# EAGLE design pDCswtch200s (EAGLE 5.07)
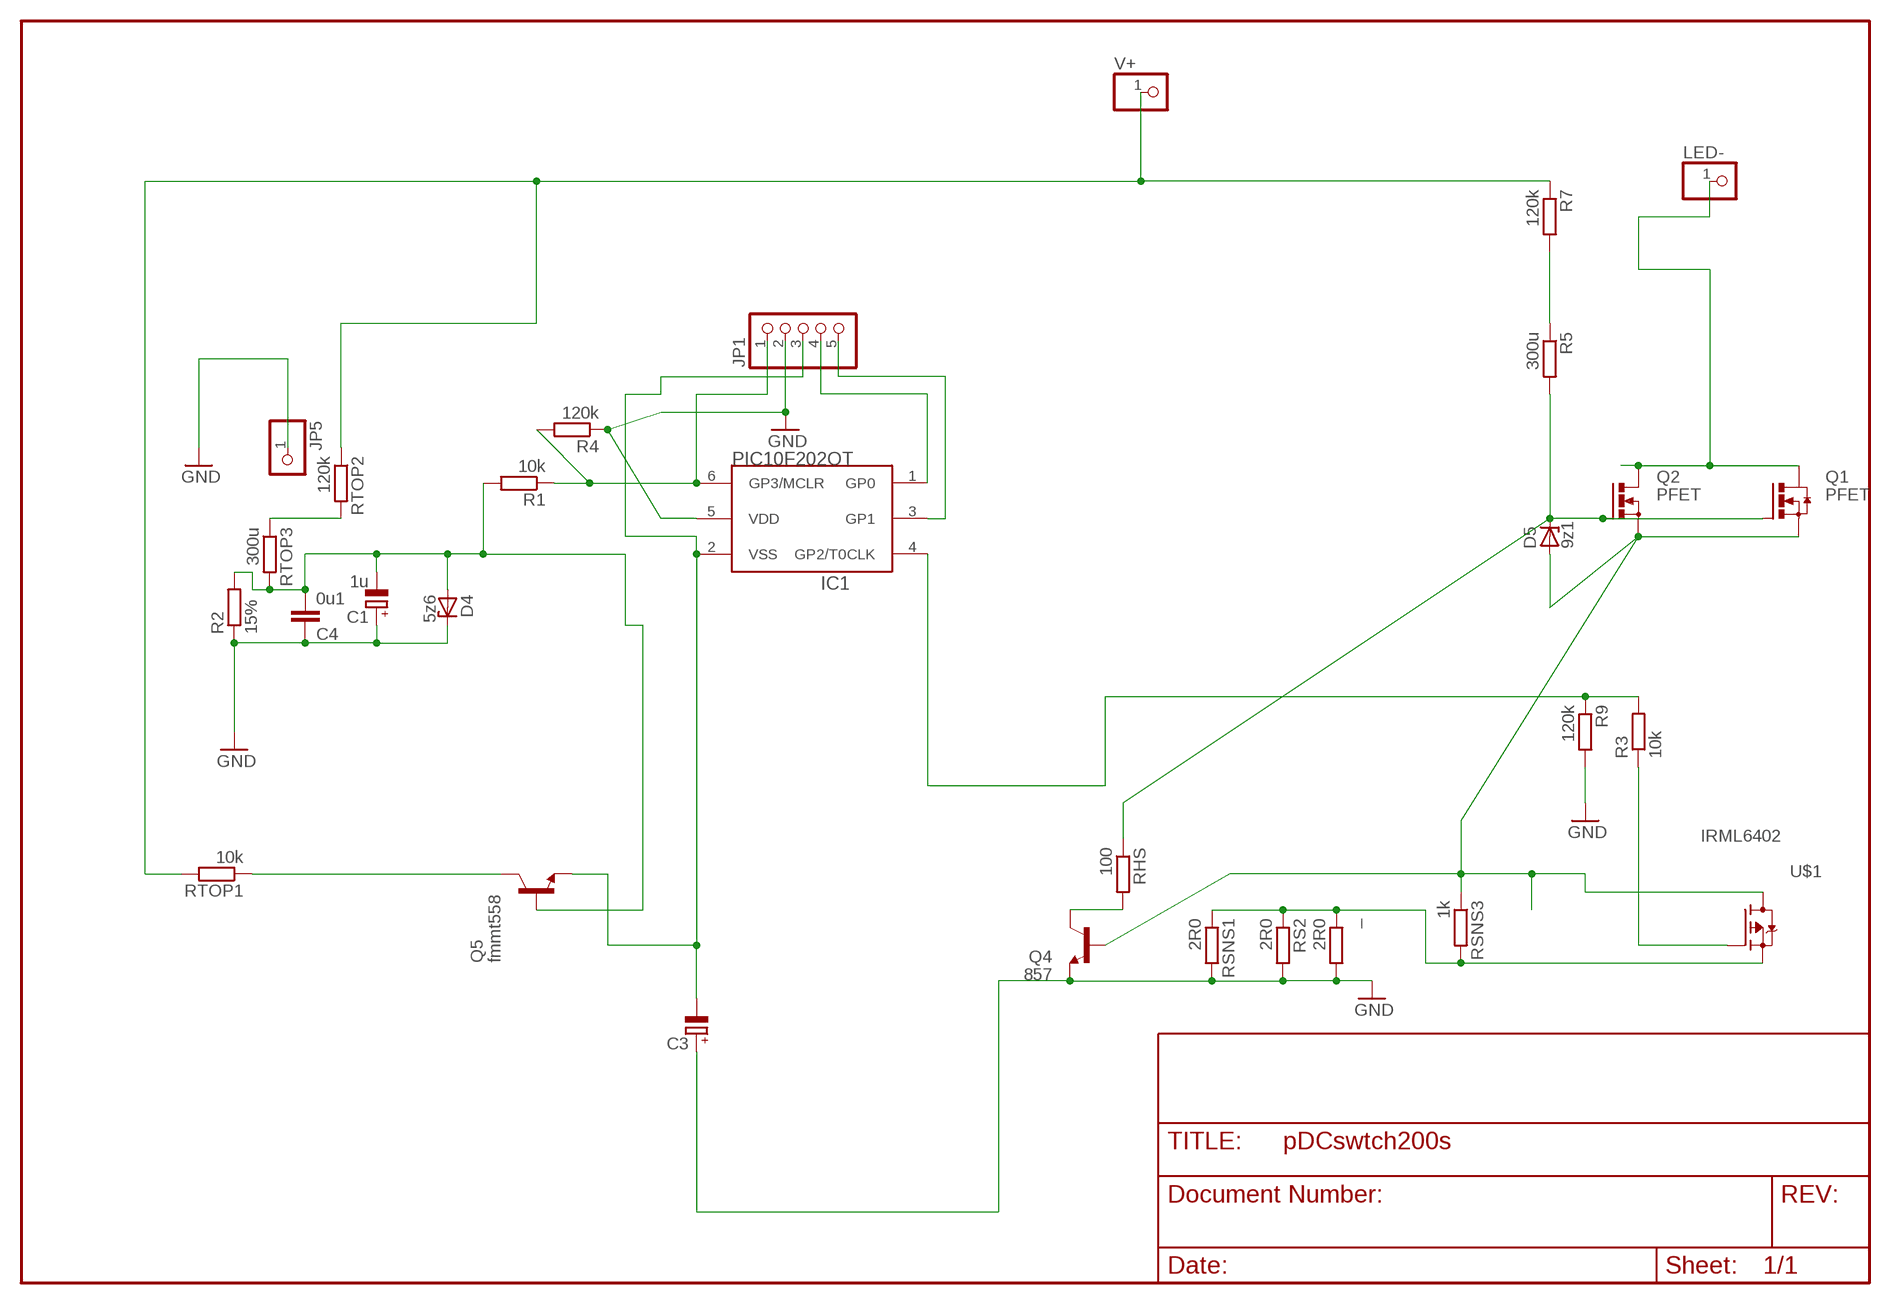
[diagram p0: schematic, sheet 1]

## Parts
_  2R0  R-EU_R1210  [R1210]
C1  1u  CPOL-EUSMCA  [SMC_A]
C3  CPOL-EUE2,5-6E  [E2,5-6E]
C4  0u1  C-EUC0805  [C0805]
D4  5z6  ZENER-DIODESOD80C  [SOD80C]
D5  9z1  ZENER-DIODESOD80C  [SOD80C]
IC1  PIC10F202OT  [SOT23-6]
JP1  PINHD-1X5/90  [1X05/90]
JP5  PINHD-1X11MM6  [1X1MM8]
LED-  PINHD-1X11MM6  [1X1MM8]
Q1  PFET  N-HEXFET_DPAK-  [TO252]
Q2  PFET  BUZ11BV  [TO220BV]
Q4  857  BC847ASMD  [SOT23]
Q5  fmmt558  BC847ALT1SMD  [SOT23]
R1  10k  R-EU_R0805  [R0805]
R2  15%  R-EU_R0805  [R0805]
R3  10k  R-EU_R0805  [R0805]
R4  120k  R-EU_R0805  [R0805]
R5  300u  R-EU_R1206  [R1206]
R7  120k  R-EU_R1206  [R1206]
R9  120k  R-EU_R0805  [R0805]
RHS  100  R-EU_0204/3  [0204/3]
RS2  2R0  R-EU_R1206  [R1206]
RSNS1  2R0  R-EU_R2512  [R2512]
RSNS3  1k  R-EU_R1206  [R1206]
RTOP1  10k  R-EU_R1206  [R1206]
RTOP2  120k  R-EU_R1206  [R1206]
RTOP3  300u  R-EU_R1206  [R1206]
U$1  IRML6402  IRML6402SOT23  [SOT23]
V+  PINHD-1X11MM6  [1X1MM8]

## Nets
BSW1: _.1 RS2.1 RSNS1.1 RSNS3.2 U$1.2(S)
C: Q5.3(C) RTOP1.1
CB: C1.- C4.2 D4.A Q5.1(B) R1.2 R2.2 RTOP3.2
G: D5.C Q1.1(G) Q2.G R5.2 RHS.1
GND: _.2 C1.+ C3.+ C4.1 D4.C IC1.5(VDD) JP1.2 JP5.1 Q4.2(E) R2.1 R4.1 R9.2 RS2.2 RSNS1.2
GP2: IC1.4(GP2/T0CLK) R3.2 R9.1
LED+: LED-.1 Q1.3(D) Q2.D
N$3: IC1.6(GP3/MCLR) JP1.1 R1.1 R4.2
N$4: R5.1 R7.2
N$5: R3.1 U$1.1(G)
N$7: Q4.3(C) RHS.2
N$9: RTOP2.2 RTOP3.1
N$10: IC1.1(GP0) JP1.4
N$12: IC1.3(GP1) JP1.5
S: D5.A Q1.2(S) Q2.S Q4.1(B) RSNS3.1 U$1.3(D)
VPLUS: R7.1 RTOP1.2 RTOP2.1 V+.1
VSS-: C3.- IC1.2(VSS) JP1.3 Q5.2(E)

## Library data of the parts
_ R3 R5 R7 RHS RS2 RSNS1 RSNS3 RTOP1-RTOP3 = rcl:R-EU_: RESISTOR, European symbol
C1 C3 = rcl:CPOL-EU: POLARIZED CAPACITOR, European symbol
C4 = rcl:C-EU: CAPACITOR, European symbol
D4 D5 = diode:ZENER-DIODE: Z-Diode
IC1 = microchip-5:PIC10F20*: uPC nW 0,25/0,5k Program Flash memory
JP1 = pinhead:PINHD-1X5: PIN HEADER
JP5 LED- V+ = pinhead:PINHD-1X1: PIN HEADER
Q1 = transistor-power:N-HEXFET_?-*: HEXFET® Power MOSFET
Q2 = transistor-power:BUZ11: N-CHANNEL MOS FET
Q4 Q5 = transistor-npn:BC847*: NPN Transistor
R1 R2 R4 R9 = rcl-2:R-EU_: RESISTOR, European symbol
U$1 = transistor-fet:IRML6402

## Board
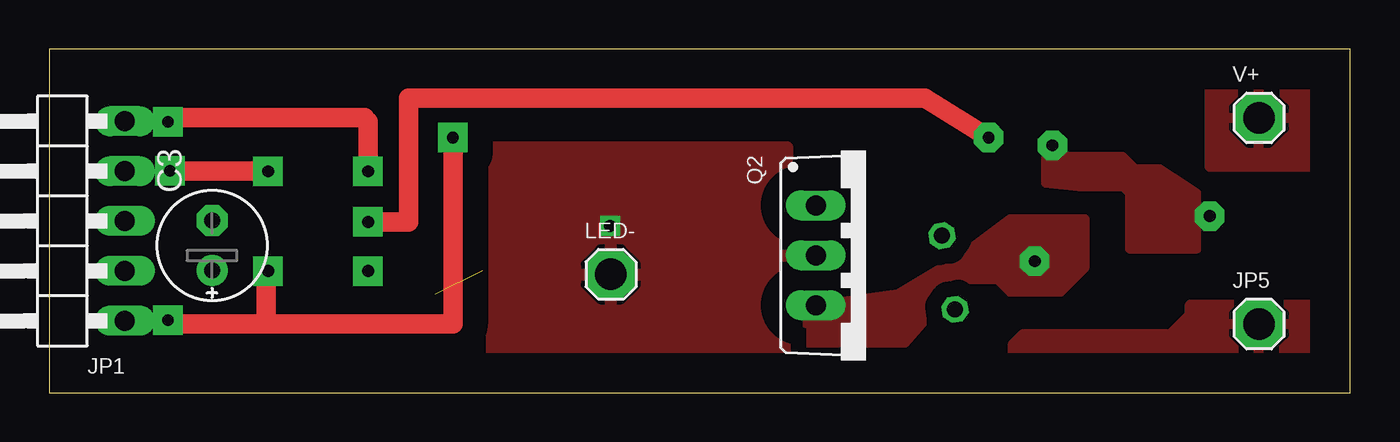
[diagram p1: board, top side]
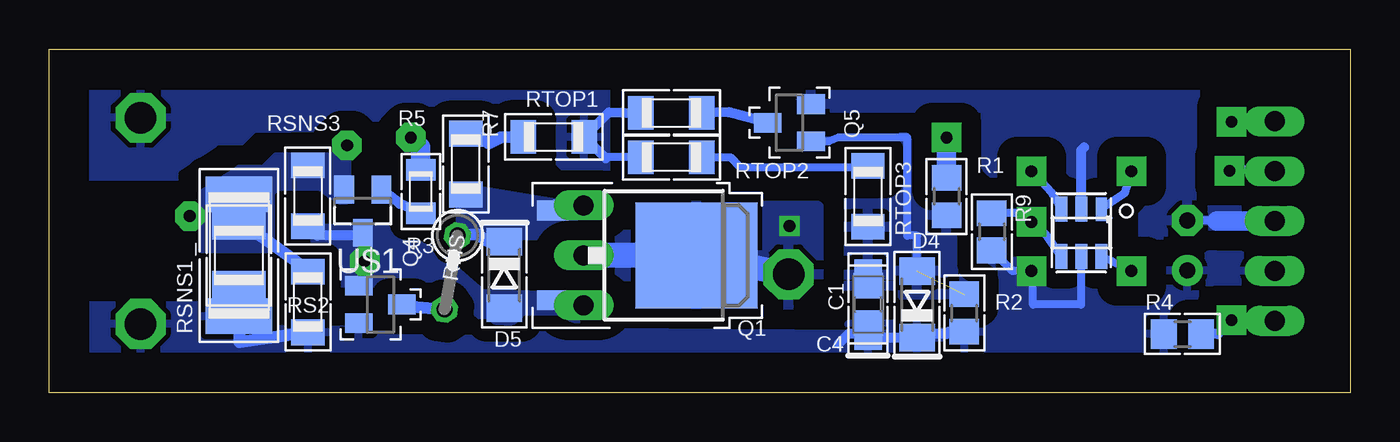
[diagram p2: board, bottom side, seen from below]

Size 66.2 x 17.5 mm. Coordinates in mm from the lower left corner, seen from the top.
Outline: 0,0 66.2,0 66.2,17.5 0,17.5 0,0
Copper layers (1*16): Top 0.035mm / dielectric 1.5mm / Bottom 0.035mm
Design rules "default *": minimum track width 10mil, minimum drill 24mil, track to track 8mil, track to pad 8mil, pad to pad 8mil, via to via 8mil, smd to smd 8mil, copper to edge 80mil, drill to drill 8mil, minimum pad ring 10mil, minimum via ring 8mil, stop-mask expansion 4mil, vias tented up to drill 0mil, thermal gap 10mil

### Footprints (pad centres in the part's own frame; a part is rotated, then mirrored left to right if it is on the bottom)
R1210 = smd 1.4 x 2.7: 1 -1.5,0; 2 1.5,0
SMC_A = smd 1.6 x 1.4: + -1.5,0; - 1.5,0
E2,5-6E = drill 0.813 pad 1.575 round: + -1.27,0 | drill 0.813 pad 1.575 octagon: - 1.27,0
C0805 = smd 1.3 x 1.5: 1 -0.95,0; 2 0.95,0
SOD80C = smd 1.4 x 1.8: A 1.7,0; C -1.7,0
SOT23-6 = smd 0.55 x 1.2: 1 -1.016,-1.2 | smd 0.6 x 1.27: 2 0,-1.2; 3 1.016,-1.2; 4 1.016,1.2; 5 0,1.2; 6 -1.016,1.2
1X05/90 = drill 1.016 long: 1 -5.08,-3.81; 2 -2.54,-3.81; 3 0,-3.81; 4 2.54,-3.81; 5 5.08,-3.81
1X1MM8 = drill 1.6 pad 2.54 octagon: 1 0,0
TO252 = smd 1 x 1.6: 1 -2.28,-3.53; 2 2.28,-3.53 | smd 5.4 x 6.2: 3 0,3.77
TO220BV = drill 1.016 long: D 0,-2.54; G -2.54,-2.54; S 2.54,-2.54
SOT23 = smd 1 x 1.4: 1 -0.95,-1.1; 2 0.95,-1.1; 3 0,1.1
R0805 = smd 1.3 x 1.5: 1 -0.95,0; 2 0.95,0
R0805' = smd 1.1 x 1.5: 1 -1.1,0; 2 1.1,0
R1206 = smd 1.3 x 1.7: 1 -1.55,0; 2 1.55,0
0204/3 = drill 0.813 octagon: 1 -1.27,0; 2 2.54,0
R2512 = smd 1.8 x 3.4: 1 -3.1,0; 2 3.1,0

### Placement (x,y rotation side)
_  56.54,7 270 bottom
C1  24.54,4.5 90 bottom
C3  8.29,7.5 90 top
C4  24.54,4.5 90 bottom
D4  22.04,4.5 90 bottom
D5  43.04,6 270 bottom
IC1  13.69,8.15 180 bottom
JP1  0.04,8.75 90 top
JP5  61.54,3.5 0 top
LED-  28.57,6.03 0 top
Q1  37.04,7 270 bottom
Q2  41.54,7 270 top
Q4  49.34,4.5 270 bottom
Q5  28.54,13.75 90 bottom
R1  20.54,10 270 bottom
R2  19.64,4.06 90 bottom
R3  10k  [R0805']  47.29,10.25 90 bottom
R4  8.54,3 0 bottom
R5  45,11.65 270 bottom
R7  40.52,13.03 180 bottom
R9  18.24,8.2 270 bottom
RHS  45.64,6.75 260 bottom
RS2  53.02,4.63 270 bottom
RSNS1  56.54,7 270 bottom
RSNS3  53.04,10.03 90 bottom
RTOP1  34.54,14.25 180 bottom
RTOP2  34.54,12 0 bottom
RTOP3  24.54,10 270 bottom
U$1  50.24,9.25 180 bottom
V+  61.54,14 0 top

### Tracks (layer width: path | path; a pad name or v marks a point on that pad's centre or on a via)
BSW1  (via drill 0.6 pad 1.5)
  Bottom 0.61: RS2.1 53.62,6.68 55.43,7.99 55.93,8.23 RSNS1.1
  other vias: 59.04,9 51.04,12.6
  pour Bottom (isolate 0.813, rank 2, no thermals): 58.42,7.3 58.42,10.16 56.52,11.43 55.24,11.43 54.61,12.06 51.04,12.06 51.04,9.66 51.62,9.84 52.39,10.48 54.61,10.48 54.93,10.16 54.93,7.3
  pour Top (isolate 0.813, rank 2, no thermals): 58.42,7.3 58.42,10.16 56.52,11.43 55.24,11.43 54.61,12.06 51.44,12.06 50.66,11.93 50.66,10.66 52.39,10.48 54.61,10.48 54.93,10.16 54.93,7.3
C
  Bottom 0.5: RTOP1.1 31.63,14.29 Q5.3
CB  (1 unrouted)
  Bottom 0.406: Q5.1 26.54,12.8 26.04,13 22.54,13 22.54,8 22.04,8 D4.A
  pour Bottom (isolate 1, rank 3): 26.04,13.5 27.54,12.5 25.54,11 25.54,5 19.04,5 19.04,8.5 20.04,9.5 23.04,13.5
G
  Bottom 0.61: RHS.1 44.4,8.07 43.93,7.73 D5.C 43.43,7.87 | Q2.G 40.41,9.57 Q1.1
  pour Bottom (isolate 1, rank 2, no thermals): 39.54,8 45.54,8 45.54,10.5 39.54,9.5
GND  (via drill 0.6 pad 1.5)
  Bottom 0.406: IC1.5 13.69,4.5 16.14,4.5 16.14,6.12 v16.22,6.2 17.19,6.2 R9.2
  Bottom 0.5: R2.1 20.43,3.11 20.54,3 21.84,3 D4.C 24.34,2.8 C1.+ 25.54,3 26.04,2.5
  Bottom 0.61: _.2 RSNS1.2 56.52,2.58 RS2.2
  pour Bottom (isolate 1): 57.15,4.45 64.77,4.45 64.77,1 3.91,1 2.87,7.12 7.31,7.12 18.73,7.03 18.7,3.51 25.54,3.5 25.04,3 57.29,3.25
  pour Top (rank 2): 58.04,4.5 65.04,4.5 65.04,1.5 49.04,1.5 49.04,2.5 49.54,3 57.04,3 58.04,4
GP2  (via drill 0.6 pad 1.5)
  Top 1: v47.79,13 44.54,15 18.29,15 18.29,8.7 v16.22,8.7
  Bottom 0.406: IC1.4 15.49,8.05 v16.22,8.7 16.22,9.15 R9.1
  Bottom 1: R3.2 47.29,12.5 v47.79,13
LED+  (via drill 0.6)
  Bottom 1.27: Q2.D Q1.3 LED-.1
  other vias: 28.54,8.5
  pour Top (isolate 1.27): 22.54,12.5 37.54,12.5 37.46,8.26 37.46,1.27 22.54,1.5
  pour Bottom (isolate 1, rank 4): 27.04,9.5 37.54,9.5 37.46,5.75 37.54,4 27.04,4
N$3  (via drill 0.6 pad 1.5)
  Top 0.406: 11.04,6.1 v11.14,6.2 | v6.04,3.7 6.24,3.5
  Top 1: v20.54,13 20.54,3.5 11.04,3.5 | 11.04,3.5 11.04,6.1 | 6.24,3.5 11.04,3.5
  Bottom 0.406: JP1.1 6.04,3.67 v6.04,3.7 | v11.14,6.2 12.12,6.7 IC1.6 | R1.1 20.5,11.06 20.54,11.5
  Bottom 0.5: R4.2 6.74,3 v6.04,3.7
  Bottom 1: v20.54,13 20.54,11.5
N$4
  Bottom 0.61: R7.2 43.21,12.99 43.81,12.7 44.62,13.34 R5.1
N$5
  Bottom 0.5: R3.1 48.37,9.64 U$1.1
N$7
  Bottom 0.61: Q4.3 47.76,4.41 RHS.2
N$9
  Bottom 0.406: RTOP2.2 31.54,12 31.04,11.5 24.59,11.5 RTOP3.1
N$10  (via drill 0.6 pad 1.5)
  Top 1: v6.14,11.3 v11.14,11.28
  Bottom 0.406: IC1.1 11.49,10.15 v11.14,11.28 | v6.14,11.3 4.06,11.5 JP1.4
N$12  (via drill 0.6 pad 1.5)
  Top 0.406: v6.04,13.8 6.24,14 | 16.04,14 16.22,13.82
  Top 1: 6.24,14 16.04,14 | 16.22,13.82 v16.22,11.28
  Bottom 0.406: JP1.5 6.04,13.83 v6.04,13.8 | IC1.3 15.21,10.2 15.71,10.77 v16.22,11.28
S  (via drill 0.6 pad 1.5)
  Bottom 0.5: RSNS3.1 53.02,8.47 52.54,8 50.39,8 U$1.3
  Bottom 0.61: Q1.2 39.55,4.81 Q2.S
  other vias: 50.14,6.7
  pour Bottom (isolate 0.813, rank 3, no thermals): 39.37,4.95 44.18,5.08 46.35,6.99 48.89,8.39 52.7,8.39 52.7,6.35 51.44,5.58 48.89,5.58 48.26,5.71 46.35,5.71 43.95,3.67 39.37,3.54
  pour Top (isolate 0.813, rank 3, no thermals): 38.54,4.45 43.18,5.08 46.35,6.99 48.89,8.89 52.7,8.89 52.7,6.35 51.44,5.08 48.89,5.08 48.26,5.71 46.35,5.71 43.54,2.5 38.54,2.5
VPLUS
  Bottom 0.406: RTOP2.1 37.95,12 38.24,12.3
  Bottom 0.5: 37.88,11.93 38.24,12.3 R7.1 37.71,14.29 RTOP1.2
  pour Bottom (isolate 1.016, rank 3): 37.83,10.84 37.83,16.5 65.41,16.5 65.54,11 59.04,11 47.04,14 40.54,14 40.54,12 39.54,11
  pour Top (rank 2): 59.04,15.5 64.54,15.5 65.04,15 65.04,11.5 59.04,11.5
VSS-
  Bottom 0.406: 6.79,8.75 6.79,8.77 C3.-
  Bottom 0.5: IC1.2 13.69,12.35 13.54,12.5
  Bottom 1: JP1.3 6.79,8.75
  pour Bottom (isolate 1, rank 2): 30.04,16 29.54,16.5 7.54,16.5 7.04,16 7.04,10 3.04,10 3.04,7.5 10.04,7.5 10.54,8 10.54,11 18.04,11 18.54,11.5 18.54,14.5 28.54,14.5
